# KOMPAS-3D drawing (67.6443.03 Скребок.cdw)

Referenced files: Скребок.cdw
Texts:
  Скребок
  *Размеры для справок.
  Допускается изготавливать из трубы ГОСТ 8734-75. Материал
  трубы сталь 09Г2С.
  Шероховатость поверхностей реза  6,3 .
  Труба НКТ89 7
  ГОСТ 633-80
  Нач. КО
Dimensions and other numbers on the sheet: 89; 76; 4; 28; 56; 44; 1:1; 1; 0,026; 0; 2; 3; 5; 6; 7; 8; 9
